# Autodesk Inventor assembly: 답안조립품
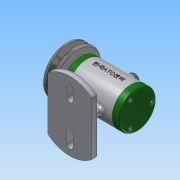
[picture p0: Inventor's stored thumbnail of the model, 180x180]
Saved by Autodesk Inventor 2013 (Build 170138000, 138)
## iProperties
Created: 2017-12
Part Number: 답안조립품
Document SubType Name: Assembly
Designer: Administrator
Author: Administrator
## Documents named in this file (14)
- C:\Users\Administrator\Desktop\471208V1030\답안조립품.iam
- C:\Users\Administrator\Desktop\471208V1030\V벨트풀리.ipt
- C:\Users\Administrator\Desktop\471208V1030\고무캡.ipt
- C:\Users\Administrator\Desktop\471208V1030\너트 M 8.ipt
- C:\Users\Administrator\Desktop\471208V1030\뒤커버.ipt
- C:\Users\Administrator\Desktop\471208V1030\베어링 15 x 32 x 9.ipt
- C:\Users\Administrator\Desktop\471208V1030\본체.ipt
- C:\Users\Administrator\Desktop\471208V1030\볼트 M4 x 12.ipt
- C:\Users\Administrator\Desktop\471208V1030\스프링와셔 8.ipt
- C:\Users\Administrator\Desktop\471208V1030\앞커버.ipt
- C:\Users\Administrator\Desktop\471208V1030\오일 실 15 25 7.ipt
- C:\Users\Administrator\Desktop\471208V1030\와셔 8x17.ipt
- C:\Users\Administrator\Desktop\471208V1030\축.ipt
- C:\Users\Administrator\Desktop\471208V1030\키 3 x 3 x 12.ipt
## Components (2 placed, 2 different names)
1. 고무캡:1
2. V벨트풀리:1
